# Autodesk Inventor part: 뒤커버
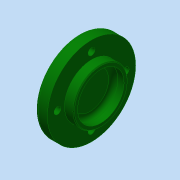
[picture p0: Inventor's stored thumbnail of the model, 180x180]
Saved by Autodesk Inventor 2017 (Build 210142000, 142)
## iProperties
Created: 2015-12
Part Number: 뒤커버
Material: 알루미늄 6061
Document SubType Name: Modeling
Designer: mduedu
Density: 2.71 g/cm^3
Appearance: 진녹색
Author: mduedu
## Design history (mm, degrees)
sketch "스케치1"
  geometry: L1 (0, 0)-(14, 0); L2 (14, 0)-(14, 17.5); L3 (14, 17.5)-(8, 17.5); L4 (8, 17.5)-(8, 28.5); L5 (8, 28.5)-(0, 28.5); L6 (0, 28.5)-(0, 0)
  constraints: 12 end point, 4 parallel, 1 horizontal, 1 perpendicular
  dimensions: "d0" = 14 distance between parallel lines of L2 L6; "d2" = 8 distance of L4.end L5.end; "d3" = 57 diameter of L5 L1; "d4" = 35 diameter of L3 L1
revolve "회전1" sketch "스케치1" stored, may be unused: angle "d5" = 90 deg
hole "구멍1" diameter "d8" = 30; stored, may be unused: countersink angle "d12" = 90 deg, drill point angle "d14" = 0 deg; dims "d9" = 6, "d10" = 4, "d11" = 2, "d13" = 7, "d39" = 10, "d40" = 10
fillet "모깎기3" dims "d38" = 2
fillet "모깎기4" dims "d41" = 3
chamfer "모따기2" distance "d42" = 0.5; stored, may be unused: second distance "d43" = 2, angle "d44" = 45 deg
sketch "스케치2" dims "d45" = 42
  geometry: 6 further points
  constraints: 2 vertical alignment, 1 coincident, 7 other
  dimensions: "d48" = 360 deg dimension on point (0, 0) point (0, 21) (derived)
sketch "스케치3" dims "d57" = 44
  geometry: C1 r 26.5 at (0, 0) reference; 5 further points
  constraints: 1 coincident, 1 horizontal alignment, 2 other
hole "구멍4" sketch "스케치3" at (-22, 0), (0, -22), (22, 0), (0, 22) diameter "d50" = 4.5; stored, may be unused: countersink angle "d54" = 90 deg, drill point angle "d56" = 0 deg; dims "d51" = 6, "d52" = 8, "d53" = 4.6, "d55" = 8
node "솔리드1"
